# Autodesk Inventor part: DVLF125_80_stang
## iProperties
Created: 2010-04
Part Number: DVLF125_80_stang
Document SubType Name: Modeling
Designer: TB
Mass: 1748.33 g
Surface Area: 998.297 cm^2
Volume: 1748.33 cm^3
Density: 1 g/cm^3
Author: TB
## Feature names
1. Revolution1
2. Fillet1
3. Revolution2
